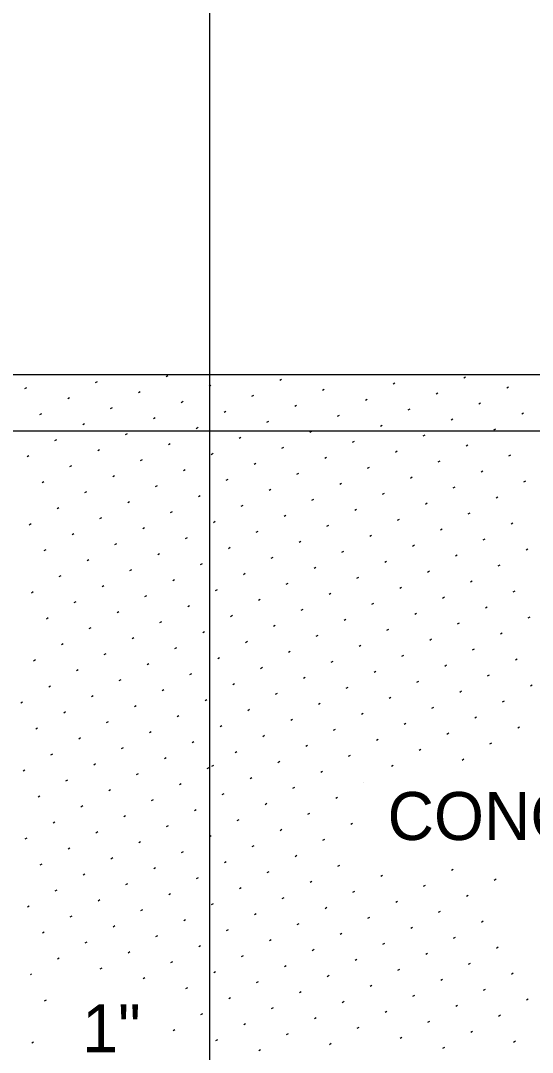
# Model space of a CAD drawing. Extents: x 99862 to 104211, y 98939 to 105076.
# Drawn here: x 101994.4 to 102164.9, y 104037.6 to 104381.5 of the extents above; entities that cross this region are included whole.
import ezdxf

# ---------------------------------------------------------------- set-up
doc = ezdxf.new("R2010")
doc.units = 0
for name, color, linetype in [('Level 1', 7, 'Continuous'), ('Level 15', 7, 'Continuous'), ('Level 20', 7, 'Continuous'), ('Level 3', 7, 'Continuous'), ('Level 6', 7, 'Continuous')]:
    doc.layers.add(name, color=color, linetype=linetype)

msp = doc.modelspace()

# ---------------------------------------------------------------- linework, layer by layer
at = {"layer": 'Level 1'}
for p, q in [((101394.64, 104263.53), (102106.49, 104263.53)), ((102106.49, 104263.53), (102481.5, 104263.53))]:
    msp.add_line(p, q, dxfattribs=at)
msp.add_ellipse((102063.85, 104535.63), major_axis=(0, -590.4), ratio=0.83118, start_param=0, end_param=1.074783, dxfattribs=at)
msp.add_ellipse((102063.85, 104535.63), major_axis=(0, -590.4), ratio=0.83118, start_param=0, end_param=1.074783, dxfattribs=at)
at = {"layer": 'Level 15'}
for p, q in [((102057.49, 104263.53), (102057.49, 104724.41)), ((102057.49, 103945.23), (102057.49, 104263.53))]:
    msp.add_line(p, q, dxfattribs=at)
at = {"layer": 'Level 3'}
for p, q in [((102019.38, 104260.86), (102019.99, 104261.21)), ((102042.92, 104262.9), (102043.52, 104263.25)), ((102080.72, 104261.63), (102081.33, 104261.98)), ((102142.06, 104262.41), (102142.66, 104262.76)), ((101995.85, 104258.82), (101996.45, 104259.17)), ((102033.65, 104257.55), (102034.26, 104257.9)), ((102057.18, 104259.59), (102057.79, 104259.94)), ((102094.99, 104258.32), (102095.59, 104258.67)), ((102118.52, 104260.37), (102119.13, 104260.72)), ((102156.33, 104259.1), (102156.93, 104259.45)), ((102010.11, 104255.51), (102010.72, 104255.86)), ((102047.92, 104254.24), (102048.52, 104254.59)), ((102071.45, 104256.28), (102072.06, 104256.63)), ((102109.26, 104255.01), (102109.86, 104255.36)), ((102132.79, 104257.06), (102133.4, 104257.41)), ((102024.38, 104252.2), (102024.99, 104252.55)), ((102062.18, 104250.93), (102062.79, 104251.28)), ((102085.72, 104252.97), (102086.33, 104253.32)), ((102123.52, 104251.71), (102124.13, 104252.06)), ((102147.06, 104253.75), (102147.66, 104254.1)), ((102161.33, 104250.44), (102161.93, 104250.79)), ((102000.85, 104250.16), (102001.45, 104250.51)), ((102038.65, 104248.89), (102039.26, 104249.24)), ((102076.45, 104247.62), (102077.06, 104247.97)), ((102099.99, 104249.66), (102100.59, 104250.01)), ((102137.79, 104248.4), (102138.4, 104248.75)), ((102015.11, 104246.85), (102015.72, 104247.2)), ((102029.38, 104243.54), (102029.99, 104243.89)), ((102052.92, 104245.58), (102053.52, 104245.93)), ((102090.72, 104244.31), (102091.33, 104244.66)), ((102114.26, 104246.35), (102114.86, 104246.7)), ((102152.06, 104245.09), (102152.66, 104245.44)), ((102005.85, 104241.5), (102006.45, 104241.85)), ((102043.65, 104240.23), (102044.26, 104240.58)), ((102067.18, 104242.27), (102067.79, 104242.62)), ((102104.99, 104241), (102105.59, 104241.35)), ((102128.52, 104243.04), (102129.13, 104243.39)), ((102020.11, 104238.19), (102020.72, 104238.54)), ((102057.92, 104236.92), (102058.52, 104237.27)), ((102081.45, 104238.96), (102082.06, 104239.31)), ((102119.26, 104237.69), (102119.86, 104238.04)), ((102142.79, 104239.74), (102143.4, 104240.09)), ((101996.58, 104236.15), (101997.18, 104236.5)), ((102034.38, 104234.88), (102034.99, 104235.23)), ((102072.18, 104233.61), (102072.79, 104233.96)), ((102095.72, 104235.65), (102096.33, 104236)), ((102133.52, 104234.38), (102134.13, 104234.73)), ((102157.06, 104236.43), (102157.66, 104236.78)), ((102010.85, 104232.84), (102011.45, 104233.19)), ((102048.65, 104231.57), (102049.26, 104231.92)), ((102086.45, 104230.3), (102087.06, 104230.65)), ((102109.99, 104232.34), (102110.59, 104232.69)), ((102147.79, 104231.08), (102148.4, 104231.43)), ((102001.58, 104227.49), (102002.18, 104227.84)), ((102025.11, 104229.53), (102025.72, 104229.88)), ((102062.92, 104228.26), (102063.52, 104228.61)), ((102100.72, 104226.99), (102101.33, 104227.34)), ((102124.26, 104229.03), (102124.86, 104229.38)), ((102162.06, 104227.77), (102162.66, 104228.12)), ((102015.85, 104224.18), (102016.45, 104224.53)), ((102039.38, 104226.22), (102039.99, 104226.57)), ((102053.65, 104222.91), (102054.26, 104223.26)), ((102077.18, 104224.95), (102077.79, 104225.3)), ((102114.99, 104223.68), (102115.59, 104224.03)), ((102138.52, 104225.72), (102139.13, 104226.07)), ((102030.11, 104220.87), (102030.72, 104221.22)), ((102067.92, 104219.6), (102068.52, 104219.95)), ((102091.45, 104221.64), (102092.06, 104221.99)), ((102129.26, 104220.37), (102129.86, 104220.72)), ((102152.79, 104222.41), (102153.4, 104222.76)), ((102006.58, 104218.83), (102007.18, 104219.18)), ((102044.38, 104217.56), (102044.99, 104217.91)), ((102082.18, 104216.29), (102082.79, 104216.64)), ((102105.72, 104218.33), (102106.33, 104218.68)), ((102143.52, 104217.06), (102144.13, 104217.41)), ((101997.31, 104213.48), (101997.92, 104213.83)), ((102020.85, 104215.52), (102021.45, 104215.87)), ((102058.65, 104214.25), (102059.26, 104214.6)), ((102096.45, 104212.98), (102097.06, 104213.33)), ((102119.99, 104215.02), (102120.59, 104215.37)), ((102157.79, 104213.75), (102158.4, 104214.1)), ((102011.58, 104210.17), (102012.18, 104210.52)), ((102035.11, 104212.21), (102035.72, 104212.56)), ((102072.92, 104210.94), (102073.52, 104211.29)), ((102110.72, 104209.67), (102111.33, 104210.02)), ((102134.26, 104211.71), (102134.86, 104212.06)), ((102025.85, 104206.86), (102026.45, 104207.21)), ((102049.38, 104208.9), (102049.99, 104209.25)), ((102087.18, 104207.63), (102087.79, 104207.98)), ((102124.99, 104206.36), (102125.59, 104206.71)), ((102148.52, 104208.4), (102149.13, 104208.75)), ((102002.31, 104204.82), (102002.92, 104205.17)), ((102040.11, 104203.55), (102040.72, 104203.9)), ((102063.65, 104205.59), (102064.26, 104205.94)), ((102077.92, 104202.28), (102078.52, 104202.63)), ((102101.45, 104204.32), (102102.06, 104204.67)), ((102139.26, 104203.05), (102139.86, 104203.4)), ((102162.79, 104205.09), (102163.4, 104205.44)), ((102016.58, 104201.51), (102017.18, 104201.86)), ((102054.38, 104200.24), (102054.99, 104200.59)), ((102092.18, 104198.97), (102092.79, 104199.32)), ((102115.72, 104201.01), (102116.33, 104201.36)), ((102153.52, 104199.74), (102154.13, 104200.09)), ((102007.31, 104196.16), (102007.92, 104196.51)), ((102030.85, 104198.2), (102031.45, 104198.55)), ((102068.65, 104196.93), (102069.26, 104197.28)), ((102106.45, 104195.66), (102107.06, 104196.01)), ((102129.99, 104197.7), (102130.59, 104198.05)), ((102021.58, 104192.85), (102022.18, 104193.2)), ((102045.11, 104194.89), (102045.72, 104195.24)), ((102082.92, 104193.62), (102083.52, 104193.97)), ((102120.72, 104192.35), (102121.33, 104192.7)), ((102144.26, 104194.39), (102144.86, 104194.74)), ((101998.04, 104190.81), (101998.65, 104191.16)), ((102035.85, 104189.54), (102036.45, 104189.89)), ((102059.38, 104191.58), (102059.99, 104191.93)), ((102097.18, 104190.31), (102097.79, 104190.66)), ((102134.99, 104189.04), (102135.59, 104189.39)), ((102158.52, 104191.08), (102159.13, 104191.43)), ((102012.31, 104187.5), (102012.92, 104187.85)), ((102050.11, 104186.23), (102050.72, 104186.58)), ((102073.65, 104188.27), (102074.26, 104188.62)), ((102111.45, 104187), (102112.06, 104187.35)), ((102149.26, 104185.73), (102149.86, 104186.08)), ((102003.04, 104182.15), (102003.65, 104182.5)), ((102026.58, 104184.19), (102027.18, 104184.54)), ((102064.38, 104182.92), (102064.99, 104183.27)), ((102087.92, 104184.96), (102088.52, 104185.31)), ((102102.18, 104181.65), (102102.79, 104182)), ((102125.72, 104183.69), (102126.33, 104184.04)), ((102163.52, 104182.42), (102164.13, 104182.77)), ((102017.31, 104178.84), (102017.92, 104179.19)), ((102040.85, 104180.88), (102041.45, 104181.23)), ((102078.65, 104179.61), (102079.26, 104179.96)), ((102116.45, 104178.34), (102117.06, 104178.69)), ((102139.99, 104180.38), (102140.59, 104180.73)), ((102031.58, 104175.53), (102032.18, 104175.88)), ((102055.11, 104177.57), (102055.72, 104177.92)), ((102092.92, 104176.3), (102093.52, 104176.65)), ((102130.72, 104175.03), (102131.33, 104175.38)), ((102154.26, 104177.07), (102154.86, 104177.42)), ((102008.04, 104173.49), (102008.65, 104173.84)), ((102045.85, 104172.22), (102046.45, 104172.57)), ((102069.38, 104174.26), (102069.99, 104174.61)), ((102107.18, 104172.99), (102107.79, 104173.34)), ((102144.99, 104171.72), (102145.59, 104172.07)), ((101998.78, 104168.14), (101999.38, 104168.49)), ((102022.31, 104170.18), (102022.92, 104170.53)), ((102060.11, 104168.91), (102060.72, 104169.26)), ((102083.65, 104170.95), (102084.26, 104171.3)), ((102121.45, 104169.68), (102122.06, 104170.03)), ((102159.26, 104168.41), (102159.86, 104168.76)), ((102013.04, 104164.83), (102013.65, 104165.18)), ((102036.58, 104166.87), (102037.18, 104167.22)), ((102074.38, 104165.6), (102074.99, 104165.95)), ((102097.92, 104167.64), (102098.52, 104167.99)), ((102135.72, 104166.37), (102136.33, 104166.72)), ((102027.31, 104161.52), (102027.92, 104161.87)), ((102050.85, 104163.56), (102051.45, 104163.91)), ((102088.65, 104162.29), (102089.26, 104162.64)), ((102112.18, 104164.33), (102112.79, 104164.68)), ((102126.45, 104161.02), (102127.06, 104161.37)), ((102149.99, 104163.06), (102150.59, 104163.41)), ((102003.78, 104159.47), (102004.38, 104159.82)), ((102041.58, 104158.21), (102042.18, 104158.56)), ((102065.11, 104160.25), (102065.72, 104160.6)), ((102102.92, 104158.98), (102103.52, 104159.33)), ((102140.72, 104157.71), (102141.33, 104158.06)), ((102164.26, 104159.75), (102164.86, 104160.1)), ((101994.51, 104154.12), (101995.11, 104154.47)), ((102018.04, 104156.17), (102018.65, 104156.52)), ((102055.85, 104154.9), (102056.45, 104155.25)), ((102079.38, 104156.94), (102079.99, 104157.29)), ((102117.18, 104155.67), (102117.79, 104156.02)), ((102154.99, 104154.4), (102155.59, 104154.75)), ((102008.78, 104150.81), (102009.38, 104151.16)), ((102032.31, 104152.86), (102032.92, 104153.21)), ((102070.11, 104151.59), (102070.72, 104151.94)), ((102093.65, 104153.63), (102094.26, 104153.98)), ((102131.45, 104152.36), (102132.06, 104152.71)), ((102023.04, 104147.51), (102023.65, 104147.86)), ((102046.58, 104149.55), (102047.18, 104149.9)), ((102084.38, 104148.28), (102084.99, 104148.63)), ((102107.92, 104150.32), (102108.52, 104150.67)), ((102145.72, 104149.05), (102146.33, 104149.4)), ((101999.51, 104145.46), (102000.11, 104145.81)), ((102037.31, 104144.2), (102037.92, 104144.55)), ((102060.85, 104146.24), (102061.45, 104146.59)), ((102098.65, 104144.97), (102099.26, 104145.32)), ((102122.18, 104147.01), (102122.79, 104147.36)), ((102159.99, 104145.74), (102160.59, 104146.09)), ((102013.78, 104142.15), (102014.38, 104142.5)), ((102051.58, 104140.89), (102052.18, 104141.24)), ((102075.11, 104142.93), (102075.72, 104143.28)), ((102112.92, 104141.66), (102113.52, 104142.01)), ((102136.45, 104143.7), (102137.06, 104144.05)), ((102150.72, 104140.39), (102151.33, 104140.74)), ((102028.04, 104138.84), (102028.65, 104139.19)), ((102065.85, 104137.58), (102066.45, 104137.93)), ((102089.38, 104139.62), (102089.99, 104139.97)), ((102127.18, 104138.35), (102127.79, 104138.7)), ((102004.51, 104136.8), (102005.11, 104137.15)), ((102018.78, 104133.49), (102019.38, 104133.84)), ((102042.31, 104135.54), (102042.92, 104135.89)), ((102080.11, 104134.27), (102080.72, 104134.62)), ((102103.65, 104136.31), (102104.26, 104136.66)), ((102141.45, 104135.04), (102142.06, 104135.39)), ((101995.24, 104131.45), (101995.85, 104131.8)), ((102033.04, 104130.18), (102033.65, 104130.53)), ((102056.58, 104132.23), (102057.18, 104132.58)), ((102058.15, 104132.99), (102058.76, 104133.34)), ((102094.38, 104130.96), (102094.99, 104131.31)), ((102117.92, 104133), (102118.52, 104133.35)), ((102009.51, 104128.14), (102010.11, 104128.49)), ((102047.31, 104126.87), (102047.92, 104127.22)), ((102070.85, 104128.92), (102071.45, 104129.27)), ((102108.65, 104127.65), (102108.66, 104127.65)), ((102023.78, 104124.83), (102024.38, 104125.18)), ((102061.58, 104123.57), (102062.18, 104123.92)), ((102085.11, 104125.61), (102085.72, 104125.96)), ((102000.24, 104122.79), (102000.85, 104123.14)), ((102038.04, 104121.52), (102038.65, 104121.87)), ((102075.85, 104120.26), (102076.45, 104120.61)), ((102099.38, 104122.3), (102099.99, 104122.65)), ((102014.51, 104119.48), (102015.11, 104119.83)), ((102052.31, 104118.21), (102052.92, 104118.56)), ((102090.11, 104116.95), (102090.72, 104117.3)), ((102005.24, 104114.13), (102005.85, 104114.48)), ((102028.78, 104116.17), (102029.38, 104116.52)), ((102043.04, 104112.86), (102043.65, 104113.21)), ((102066.58, 104114.91), (102067.18, 104115.26)), ((102104.38, 104113.64), (102104.99, 104113.99)), ((102019.51, 104110.82), (102020.11, 104111.17)), ((102057.31, 104109.55), (102057.92, 104109.9)), ((102080.85, 104111.6), (102081.45, 104111.95)), ((101995.97, 104108.78), (101996.58, 104109.13)), ((102033.78, 104107.51), (102034.38, 104107.86)), ((102071.58, 104106.24), (102072.18, 104106.59)), ((102095.11, 104108.29), (102095.72, 104108.64)), ((102010.24, 104105.47), (102010.85, 104105.82)), ((102048.04, 104104.2), (102048.65, 104104.55)), ((102085.85, 104102.94), (102086.45, 104103.29)), ((102000.97, 104100.12), (102001.58, 104100.47)), ((102024.51, 104102.16), (102025.11, 104102.51)), ((102062.31, 104100.89), (102062.92, 104101.24)), ((102100.11, 104099.63), (102100.72, 104099.98)), ((102015.24, 104096.81), (102015.85, 104097.16)), ((102038.78, 104098.85), (102039.38, 104099.2)), ((102076.58, 104097.58), (102077.18, 104097.93)), ((102114.38, 104096.32), (102114.99, 104096.67)), ((102137.92, 104098.36), (102138.52, 104098.71)), ((102029.51, 104093.5), (102030.11, 104093.85)), ((102053.04, 104095.54), (102053.65, 104095.89)), ((102067.31, 104092.23), (102067.92, 104092.58)), ((102090.85, 104094.28), (102091.45, 104094.63)), ((102128.65, 104093.01), (102129.26, 104093.36)), ((102152.18, 104095.05), (102152.79, 104095.4)), ((102005.97, 104091.46), (102006.58, 104091.81)), ((102043.78, 104090.19), (102044.38, 104090.54)), ((102081.58, 104088.92), (102082.18, 104089.27)), ((102105.11, 104090.97), (102105.72, 104091.32)), ((102142.92, 104089.7), (102143.52, 104090.05)), ((101996.7, 104086.11), (101997.31, 104086.46)), ((102020.24, 104088.15), (102020.85, 104088.5)), ((102058.04, 104086.88), (102058.65, 104087.23)), ((102095.85, 104085.61), (102096.45, 104085.96)), ((102119.38, 104087.66), (102119.99, 104088.01)), ((102010.97, 104082.8), (102011.58, 104083.15)), ((102034.51, 104084.84), (102035.11, 104085.19)), ((102072.31, 104083.57), (102072.92, 104083.92)), ((102110.11, 104082.31), (102110.72, 104082.66)), ((102133.65, 104084.35), (102134.26, 104084.7)), ((102025.24, 104079.49), (102025.85, 104079.84)), ((102048.78, 104081.53), (102049.38, 104081.88)), ((102086.58, 104080.26), (102087.18, 104080.61)), ((102124.38, 104079), (102124.99, 104079.35)), ((102147.92, 104081.04), (102148.52, 104081.39)), ((102001.7, 104077.45), (102002.31, 104077.8)), ((102039.51, 104076.18), (102040.11, 104076.53)), ((102063.04, 104078.22), (102063.65, 104078.57)), ((102100.85, 104076.95), (102101.45, 104077.3)), ((102138.65, 104075.69), (102139.26, 104076.04)), ((102015.97, 104074.14), (102016.58, 104074.49)), ((102053.78, 104072.87), (102054.38, 104073.22)), ((102077.31, 104074.91), (102077.92, 104075.26)), ((102091.58, 104071.6), (102092.18, 104071.95)), ((102115.11, 104073.65), (102115.72, 104074)), ((102152.92, 104072.38), (102153.52, 104072.73)), ((102006.7, 104068.79), (102007.31, 104069.14)), ((102030.24, 104070.83), (102030.85, 104071.18)), ((102068.04, 104069.56), (102068.65, 104069.91)), ((102105.85, 104068.29), (102106.45, 104068.64)), ((102129.38, 104070.34), (102129.99, 104070.69)), ((102020.97, 104065.48), (102021.58, 104065.83)), ((102044.51, 104067.52), (102045.11, 104067.87)), ((102082.31, 104066.25), (102082.92, 104066.6)), ((102120.11, 104064.98), (102120.72, 104065.33)), ((102143.65, 104067.03), (102144.26, 104067.38)), ((101997.68, 104063.58), (101998.04, 104063.79)), ((102035.24, 104062.17), (102035.85, 104062.52)), ((102058.78, 104064.21), (102059.38, 104064.56)), ((102096.58, 104062.94), (102097.18, 104063.29)), ((102134.38, 104061.68), (102134.99, 104062.03)), ((102157.92, 104063.72), (102158.52, 104064.07)), ((102049.51, 104058.86), (102050.11, 104059.21)), ((102073.04, 104060.9), (102073.65, 104061.25)), ((102110.85, 104059.63), (102111.45, 104059.98)), ((102148.65, 104058.37), (102149.26, 104058.72)), ((102002.44, 104054.78), (102003.04, 104055.13)), ((102063.78, 104055.55), (102064.38, 104055.9)), ((102087.31, 104057.59), (102087.92, 104057.94)), ((102125.11, 104056.32), (102125.72, 104056.67)), ((102162.92, 104055.06), (102163.52, 104055.41)), ((102078.04, 104052.24), (102078.65, 104052.59)), ((102101.58, 104054.28), (102102.18, 104054.63)), ((102115.85, 104050.97), (102116.45, 104051.32)), ((102139.38, 104053.01), (102139.99, 104053.36)), ((102054.51, 104050.2), (102055.11, 104050.55)), ((102092.31, 104048.93), (102092.92, 104049.28)), ((102130.11, 104047.66), (102130.72, 104048.01)), ((102153.65, 104049.71), (102154.26, 104050.06)), ((102045.24, 104044.85), (102045.85, 104045.2)), ((102068.78, 104046.89), (102069.38, 104047.24)), ((102106.58, 104045.62), (102107.18, 104045.97)), ((102144.38, 104044.35), (102144.99, 104044.7)), ((101998.17, 104040.77), (101998.78, 104041.12)), ((102059.51, 104041.54), (102060.11, 104041.89)), ((102083.04, 104043.58), (102083.65, 104043.93)), ((102120.85, 104042.31), (102121.45, 104042.66)), ((102158.65, 104041.05), (102159.26, 104041.4)), ((102073.78, 104038.23), (102074.38, 104038.58)), ((102097.31, 104040.27), (102097.92, 104040.62)), ((102135.11, 104039), (102135.72, 104039.35))]:
    msp.add_line(p, q, dxfattribs=at)
at = {"layer": 'Level 6'}
msp.add_line((102647.84, 104244.65), (101394.64, 104244.65), dxfattribs=at)

# ---------------------------------------------------------------- texts
at = {"layer": 'Level 20'}
for s, p in [('CONCRETE PATCH', (102116.66, 104108.38)), ('1"', (102014.97, 104037.62))]:
    msp.add_text(s, height=16, dxfattribs=at).set_placement(p)

doc.saveas('drawing.dxf')
